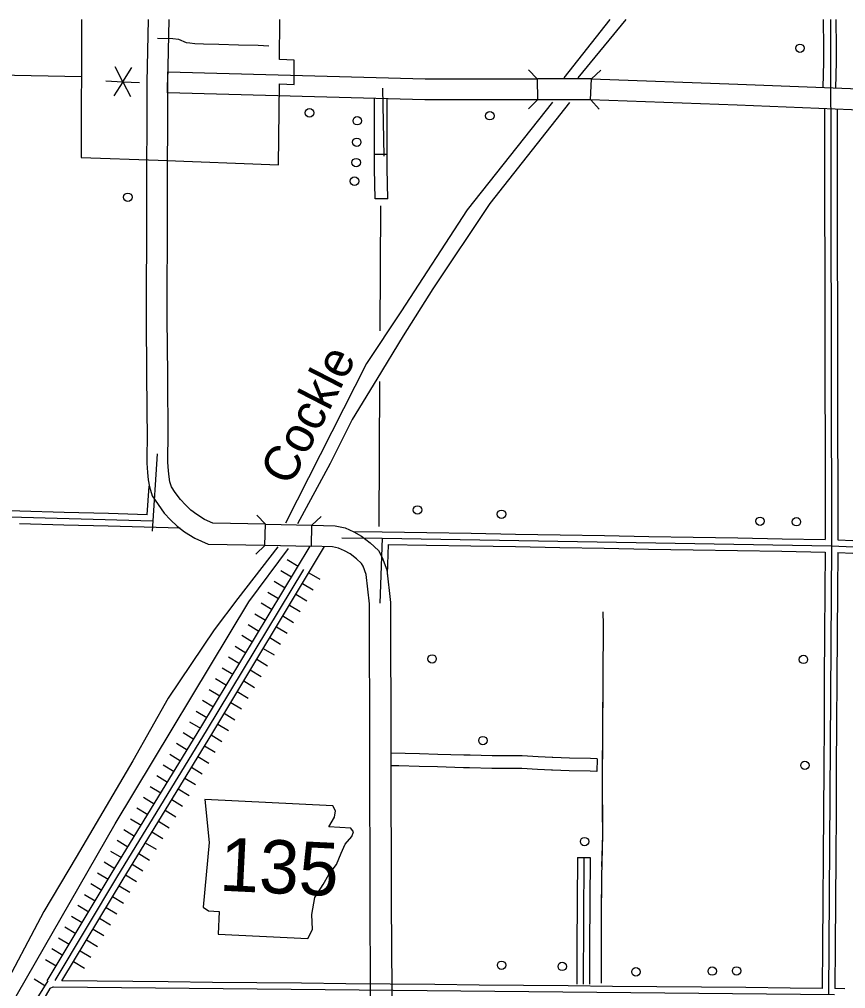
# Model space of a CAD drawing. Extents: x -4306 to 3843, y 131 to 8053.
# Drawn here: x -1822 to -251, y 6210 to 8053 of the extents above; entities that cross this region are included whole.
import ezdxf

# ---------------------------------------------------------------- set-up
doc = ezdxf.new("R2010")
doc.units = 0
for name, color, linetype in [('10', 7, 'Continuous'), ('21', 7, 'Continuous'), ('29', 7, 'Continuous'), ('32', 7, 'Continuous'), ('33', 7, 'Continuous'), ('37', 7, 'Continuous'), ('43', 7, 'Continuous'), ('46', 7, 'Continuous'), ('48', 7, 'Continuous'), ('5', 7, 'Continuous'), ('56', 7, 'Continuous'), ('6', 7, 'Continuous')]:
    doc.layers.add(name, color=color, linetype=linetype)

msp = doc.modelspace()

# ---------------------------------------------------------------- linework, layer by layer
at = {"layer": '10'}
for p, q in [((-1577, 8053), (-1579.6, 7933.8)), ((-1539.6, 7933.4), (-1537, 8053)), ((-1540, 7913.1), (-1539.4, 7953.1)), ((-1579.6, 7933.8), (-1579.9, 7691.3)), ((-1539.9, 7691.2), (-1539.6, 7933.4)), ((-837.1, 7940), (-837, 7900)), ((-746.1, 7940.2), (-836.3, 7940)), ((-734.1, 7939.8), (-746.1, 7940.2)), ((-736.1, 7899.8), (-734.1, 7939.8)), ((-734.1, 7939.8), (-455.6, 7929.7)), ((-455.6, 7929.7), (-87, 7915.2)), ((-746.8, 7900.2), (-837.2, 7900)), ((-736.1, 7899.8), (-746.8, 7900.2)), ((-457.2, 7889.8), (-736.1, 7899.8)), ((-88, 7875.2), (-457.2, 7889.8)), ((-1579.9, 7691.3), (-1580.5, 7484.2)), ((-1540.5, 7484.2), (-1539.9, 7691.2)), ((-1580.5, 7484.2), (-1579.8, 7377.2)), ((-1539.8, 7377.4), (-1540.5, 7484.2)), ((-1579.8, 7377.2), (-1579, 7253.4)), ((-1539, 7253.3), (-1539.8, 7377.4)), ((-1579, 7253.4), (-1579.2, 7227.1)), ((-1539.2, 7227), (-1539, 7253.3)), ((-1579.2, 7227.1), (-1579.2, 7209.6)), ((-1539.2, 7211.1), (-1539.2, 7227)), ((-1579.2, 7209.6), (-1577.9, 7191.8)), ((-1538, 7194.8), (-1539.2, 7211.1)), ((-1577.9, 7191.8), (-1576.8, 7177.9)), ((-1537.1, 7183), (-1538, 7194.8)), ((-1576.8, 7177.9), (-1574.4, 7164.4)), ((-1535.5, 7173.9), (-1537.1, 7183)), ((-1532.5, 7164.3), (-1535.5, 7173.9)), ((-1574.4, 7164.4), (-1569, 7146.9)), ((-1525.3, 7153.7), (-1532.5, 7164.3)), ((-1515.4, 7140), (-1525.3, 7153.7)), ((-1569, 7146.9), (-1558.1, 7130.8)), ((-1506, 7130), (-1515.4, 7140)), ((-1558.1, 7130.8), (-1546.3, 7114.5)), ((-1546.3, 7114.5), (-1534.4, 7101.7)), ((-1495.6, 7120.2), (-1506, 7130)), ((-1484.4, 7111.4), (-1495.6, 7120.2)), ((-1534.4, 7101.7), (-1521.6, 7089.8)), ((-1469.6, 7101.9), (-1484.4, 7111.4)), ((-1454.1, 7095.3), (-1469.6, 7101.9)), ((-1353.5, 7093.3), (-1454.1, 7095.3)), ((-1521.6, 7089.8), (-1507.6, 7078.8)), ((-1507.6, 7078.8), (-1488.3, 7066.4)), ((-1355, 7053.1), (-1353.5, 7093.1)), ((-1353.5, 7093.1), (-1265.3, 7091.2)), ((-1266.1, 7051.2), (-1265.5, 7091.2)), ((-1265.5, 7091.2), (-1221.5, 7090.2)), ((-1221.5, 7090.2), (-1202.6, 7086.2)), ((-1202.6, 7086.2), (-1185.9, 7078.7)), ((-1185.9, 7078.7), (-1171, 7070.8)), ((-1488.3, 7066.4), (-1462.6, 7055.5)), ((-1171, 7070.8), (-1154.7, 7058)), ((-1154.7, 7058), (-1139.3, 7043.4)), ((-1462.6, 7055.5), (-1355, 7053.3)), ((-1355, 7053.1), (-1266.1, 7051.2)), ((-1226.2, 7050.3), (-1266.1, 7051.2)), ((-1215.1, 7048), (-1226.2, 7050.3)), ((-1203.4, 7042.7), (-1215.1, 7048)), ((-1192.9, 7037.2), (-1203.4, 7042.7)), ((-1139.3, 7043.4), (-1131.8, 7029.9)), ((-1180.9, 7027.7), (-1192.9, 7037.2)), ((-1171.2, 7018.6), (-1180.9, 7027.7)), ((-1131.8, 7029.9), (-1123.4, 7006.8)), ((-1168.3, 7013.3), (-1171.2, 7018.6)), ((-1162.7, 6997.6), (-1168.3, 7013.3)), ((-1123.4, 7006.8), (-1116.2, 6944.1)), ((-1156.2, 6941.8), (-1162.7, 6997.6)), ((-1154.7, 6376.4), (-1156.2, 6941.8)), ((-1116.2, 6944.1), (-1114.6, 6374.8))]:
    msp.add_line(p, q, dxfattribs=at)
for points in [[(-1539.4, 7953.1), (-1050.4, 7939.7), (-836.3, 7940)], [(-837.2, 7900), (-1051, 7899.7), (-1540, 7913.1)], [(-1115.9, 5392.1), (-1117, 5396), (-1133.5, 5434.2), (-1148.9, 5491), (-1153.2, 5529.9), (-1154.3, 5556.1), (-1153.9, 6206.8), (-1154.7, 6376.4)], [(-1114.6, 6374.8), (-1113.9, 6206.9), (-1114.3, 5556.9), (-1113.3, 5533), (-1109.5, 5498.5), (-1095.6, 5447.4), (-1079.2, 5409.3), (-1073.9, 5390.1)]]:
    msp.add_lwpolyline(points, dxfattribs=at)
at = {"layer": '21'}
msp.add_lwpolyline([(-1469.2, 6570), (-1461, 6488.3), (-1472.4, 6365.5), (-1461.9, 6358.2), (-1441.6, 6357.2), (-1443.8, 6314), (-1273.4, 6305.6), (-1264.4, 6322.8), (-1265.8, 6351.3), (-1260.1, 6383.6), (-1244, 6408.5), (-1233.6, 6427), (-1219.1, 6446.6), (-1209.9, 6467.9), (-1202.3, 6485.1), (-1189.4, 6499.4), (-1186.2, 6508.7), (-1191.3, 6515.7), (-1233.2, 6517.8), (-1222.8, 6536.2), (-1220.9, 6548.4), (-1226, 6558)], close=True, dxfattribs=at)
at = {"layer": '29'}
for p, q in [((-1312.4, 7025.9), (-1291.9, 7013.5)), ((-1324.8, 7005.3), (-1304.3, 6993)), ((-1337.2, 6984.8), (-1316.7, 6972.4)), ((-1271.3, 7001.1), (-1250.8, 6988.8)), ((-1283.7, 6980.6), (-1263.1, 6968.2)), ((-1349.6, 6964.2), (-1329, 6951.8)), ((-1349.6, 6964.2), (-1329, 6951.8)), ((-1296.1, 6960), (-1275.5, 6947.6)), ((-1362, 6943.7), (-1341.4, 6931.3)), ((-1308.5, 6939.5), (-1287.9, 6927.1)), ((-1308.5, 6939.5), (-1287.9, 6927.1)), ((-1374.4, 6923.1), (-1353.8, 6910.7)), ((-1320.9, 6918.9), (-1300.3, 6906.5)), ((-1386.8, 6902.5), (-1366.2, 6890.2)), ((-1386.8, 6902.5), (-1366.2, 6890.2)), ((-1333.2, 6898.3), (-1312.7, 6885.9)), ((-1399.1, 6882), (-1378.6, 6869.6)), ((-1345.6, 6877.8), (-1325.1, 6865.4)), ((-1345.6, 6877.8), (-1325.1, 6865.4)), ((-1411.5, 6861.4), (-1391, 6849)), ((-1358, 6857.2), (-1337.5, 6844.8)), ((-1423.9, 6840.9), (-1403.3, 6828.5)), ((-1423.9, 6840.9), (-1403.3, 6828.5)), ((-1370.4, 6836.6), (-1349.8, 6824.3)), ((-1436.3, 6820.3), (-1415.7, 6807.9)), ((-1448.7, 6799.7), (-1428.1, 6787.3)), ((-1382.8, 6816.1), (-1362.2, 6803.7)), ((-1382.8, 6816.1), (-1362.2, 6803.7)), ((-1395.2, 6795.5), (-1374.6, 6783.1)), ((-1461.1, 6779.2), (-1440.5, 6766.8)), ((-1461.1, 6779.2), (-1440.5, 6766.8)), ((-1407.5, 6775), (-1387, 6762.6)), ((-1473.4, 6758.6), (-1452.9, 6746.2)), ((-1419.9, 6754.4), (-1399.4, 6742)), ((-1419.9, 6754.4), (-1399.4, 6742)), ((-1485.8, 6738), (-1465.3, 6725.7)), ((-1432.3, 6733.8), (-1411.8, 6721.5)), ((-1498.1, 6717.7), (-1477.6, 6705.2)), ((-1498.1, 6717.7), (-1477.6, 6705.2)), ((-1444.7, 6713.3), (-1424.1, 6700.9)), ((-1510.6, 6697.2), (-1490.1, 6684.7)), ((-1457.1, 6692.7), (-1436.7, 6680.1)), ((-1457.1, 6692.7), (-1436.7, 6680.1)), ((-1523.1, 6676.7), (-1502.6, 6664.2)), ((-1469.6, 6672.2), (-1449.2, 6659.7)), ((-1535.6, 6656.2), (-1515.2, 6643.7)), ((-1535.6, 6656.2), (-1515.2, 6643.7)), ((-1548.2, 6635.8), (-1527.7, 6623.2)), ((-1482.2, 6651.7), (-1461.7, 6639.2)), ((-1560.7, 6615.3), (-1540.2, 6602.8)), ((-1494.7, 6631.2), (-1474.2, 6618.7)), ((-1494.7, 6631.2), (-1474.2, 6618.7)), ((-1507.2, 6610.7), (-1486.7, 6598.2)), ((-1573.2, 6594.8), (-1552.7, 6582.3)), ((-1573.2, 6594.8), (-1552.7, 6582.3)), ((-1519.7, 6590.2), (-1499.2, 6577.7)), ((-1585.7, 6574.3), (-1565.2, 6561.8)), ((-1532.2, 6569.8), (-1511.7, 6557.3)), ((-1532.2, 6569.8), (-1511.7, 6557.3)), ((-1598.2, 6553.8), (-1577.7, 6541.3)), ((-1544.7, 6549.3), (-1524.2, 6536.8)), ((-1610.7, 6533.3), (-1590.2, 6520.8)), ((-1610.7, 6533.3), (-1590.2, 6520.8)), ((-1557.2, 6528.8), (-1536.8, 6516.3)), ((-1623.2, 6512.9), (-1602.8, 6500.3)), ((-1569.8, 6508.3), (-1549.3, 6495.8)), ((-1569.8, 6508.3), (-1549.3, 6495.8)), ((-1635.8, 6492.4), (-1615.3, 6479.9)), ((-1582.3, 6487.8), (-1561.8, 6475.3)), ((-1648.3, 6471.9), (-1627.8, 6459.4)), ((-1648.3, 6471.9), (-1627.8, 6459.4)), ((-1660.8, 6451.4), (-1640.3, 6438.9)), ((-1594.8, 6467.4), (-1574.3, 6454.8)), ((-1673.3, 6430.6), (-1652.8, 6418.3)), ((-1607.3, 6446.9), (-1586.8, 6434.4)), ((-1607.3, 6446.9), (-1586.8, 6434.4)), ((-1619.8, 6426.4), (-1599.3, 6413.9)), ((-1685.7, 6410.1), (-1665.1, 6397.7)), ((-1685.7, 6410.1), (-1665.1, 6397.7)), ((-1632.2, 6405.9), (-1611.6, 6393.6)), ((-1698.1, 6389.5), (-1677.5, 6377.1)), ((-1644.5, 6385.3), (-1624, 6373)), ((-1644.5, 6385.3), (-1624, 6373)), ((-1710.4, 6368.9), (-1689.8, 6356.5)), ((-1656.9, 6364.8), (-1636.3, 6352.4)), ((-1722.8, 6348.3), (-1702.2, 6336)), ((-1722.8, 6348.3), (-1702.2, 6336)), ((-1669.3, 6344.2), (-1648.7, 6331.8)), ((-1735.1, 6327.8), (-1714.5, 6315.4)), ((-1681.6, 6323.6), (-1661, 6311.3)), ((-1681.6, 6323.6), (-1661, 6311.3)), ((-1747.5, 6307.2), (-1726.9, 6294.8)), ((-1694, 6303), (-1673.4, 6290.7)), ((-1759.8, 6286.6), (-1739.3, 6274.2)), ((-1759.8, 6286.6), (-1739.3, 6274.2)), ((-1772.2, 6266), (-1751.6, 6253.7)), ((-1706.3, 6282.5), (-1685.7, 6270.1)), ((-1718.7, 6261.9), (-1698.1, 6249.5)), ((-1718.7, 6261.9), (-1698.1, 6249.5)), ((-1793.8, 6229.1), (-1773.3, 6216.5))]:
    msp.add_line(p, q, dxfattribs=at)
at = {"layer": '32'}
for p, q in [((-293.7, 8053), (-293.1, 7999.3)), ((-279.5, 8053), (-277.8, 7052)), ((-269.7, 8053), (-269.1, 7999.5)), ((-293.1, 7999.3), (-292.8, 7972.3)), ((-269.1, 7999.5), (-268.8, 7972.1)), ((-292.8, 7972.3), (-294.2, 7923.4)), ((-268.8, 7972.1), (-270.2, 7922.4)), ((-1128.2, 7793.2), (-1130.9, 7921.9)), ((-1146.4, 7880.6), (-1146.5, 7902.3)), ((-1122.4, 7880.7), (-1122.5, 7901.6)), ((-1146.6, 7852.2), (-1146.4, 7879.7)), ((-1146.4, 7879.7), (-1146.4, 7880.6)), ((-1122.6, 7852.1), (-1122.4, 7879.6)), ((-1122.4, 7879.6), (-1122.4, 7880.7)), ((-291.2, 7883.2), (-291.1, 7851.3)), ((-267.2, 7882.2), (-267.1, 7851.4)), ((-1146.6, 7807.4), (-1146.6, 7852.2)), ((-1122.6, 7807.5), (-1122.6, 7852.1)), ((-291.1, 7851.3), (-291, 7766.8)), ((-267.1, 7851.4), (-267, 7766.9)), ((-1146.5, 7796.1), (-1146.6, 7807.4)), ((-1122.5, 7796.3), (-1146.5, 7796.1)), ((-1146.3, 7768.9), (-1146.5, 7796.1)), ((-1122.5, 7796.3), (-1122.6, 7807.5)), ((-1122.3, 7769.2), (-1122.5, 7796.3)), ((-1145.2, 7711.5), (-1146.3, 7768.9)), ((-1121.2, 7711.9), (-1122.3, 7769.2)), ((-291, 7766.8), (-290.9, 7682.3)), ((-267, 7766.9), (-266.9, 7682.4)), ((-1121.2, 7711.9), (-1145.2, 7711.5)), ((-290.9, 7682.3), (-290.7, 7597.8)), ((-266.9, 7682.4), (-266.7, 7597.9)), ((-290.7, 7597.8), (-290.6, 7513.4)), ((-266.7, 7597.9), (-266.6, 7513.4)), ((-290.6, 7513.4), (-290.4, 7428.9)), ((-266.6, 7513.4), (-266.4, 7428.9)), ((-290.4, 7428.9), (-290.3, 7344.4)), ((-266.4, 7428.9), (-266.3, 7344.4)), ((-290.3, 7344.4), (-290.1, 7259.9)), ((-266.3, 7344.4), (-266.1, 7259.9)), ((-290.1, 7259.9), (-290, 7175.4)), ((-266.1, 7259.9), (-266, 7175.4)), ((-1568.5, 7080.3), (-1559.2, 7227)), ((-290, 7175.4), (-289.9, 7090.9)), ((-266, 7175.4), (-265.9, 7091)), ((-1578.6, 7111.3), (-1575.2, 7165.3)), ((-1821, 7118), (-1899.3, 7120.2)), ((-1736.6, 7115.6), (-1821, 7118)), ((-1652.1, 7113.3), (-1736.6, 7115.6)), ((-1578.6, 7111.3), (-1652.1, 7113.3)), ((-1568, 7099), (-1892.8, 7108)), ((-1737.2, 7091.6), (-1821.7, 7094)), ((-1652.8, 7089.3), (-1737.2, 7091.6)), ((-1516.2, 7085.5), (-1652.8, 7089.3)), ((-1186.6, 7079.1), (-1132, 7079)), ((-1131.8, 7079), (-1047.3, 7077.5)), ((-1047.3, 7077.5), (-962.9, 7076)), ((-962.9, 7076), (-878.4, 7074.6)), ((-289.9, 7090.9), (-289.8, 7064.2)), ((-265.9, 7091), (-265.8, 7063.5)), ((-1208.9, 7067.1), (-1132, 7067)), ((-1132, 7067), (-1136.2, 6943)), ((-1132, 7067), (-277.8, 7052)), ((-878.4, 7074.6), (-793.9, 7073.1)), ((-793.9, 7073.1), (-709.4, 7071.6)), ((-709.4, 7071.6), (-625, 7070.1)), ((-625, 7070.1), (-540.5, 7068.6)), ((-540.5, 7068.6), (-456, 7067.1)), ((-456, 7067.1), (-371.5, 7065.7)), ((-371.5, 7065.7), (-289.8, 7064.2)), ((-265.8, 7063.5), (-202.3, 7060.6)), ((-1120.4, 7054.8), (-1122.4, 6997.5)), ((-1120.4, 7054.8), (-1047.8, 7053.5)), ((-1047.8, 7053.5), (-963.3, 7052)), ((-963.3, 7052), (-878.8, 7050.6)), ((-878.8, 7050.6), (-794.3, 7049.1)), ((-794.3, 7049.1), (-709.9, 7047.6)), ((-709.9, 7047.6), (-625.4, 7046.1)), ((-625.4, 7046.1), (-540.9, 7044.6)), ((-540.9, 7044.6), (-456.4, 7043.1)), ((-456.4, 7043.1), (-372, 7041.7)), ((-372, 7041.7), (-289.9, 7040.2)), ((-289.9, 7040.2), (-290.4, 6967.6)), ((-277.8, 7052), (-283.5, 6198.8)), ((-277.8, 7052), (484, 7017.2)), ((-265.9, 7039.5), (-266.4, 6967.4)), ((-265.9, 7039.5), (-203.4, 7036.6)), ((-1281.6, 7007.3), (-1466.4, 6700.5)), ((-290.4, 6967.6), (-290.9, 6883.1)), ((-266.4, 6967.4), (-266.9, 6883)), ((-290.9, 6883.1), (-291.5, 6798.6)), ((-266.9, 6883), (-267.5, 6798.5)), ((-291.5, 6798.6), (-292, 6714.1)), ((-267.5, 6798.5), (-268, 6714)), ((-292, 6714.1), (-292.6, 6629.7)), ((-268, 6714), (-268.6, 6629.5)), ((-1466.4, 6700.5), (-1634.9, 6424.7)), ((-1061.1, 6656.6), (-1115.4, 6657.9)), ((-1026, 6655.7), (-1061.1, 6656.6)), ((-976.6, 6654.2), (-1026, 6655.7)), ((-965, 6653.9), (-976.6, 6654.2)), ((-922.9, 6652.7), (-965, 6653.9)), ((-892.5, 6652.7), (-922.9, 6652.7)), ((-865.8, 6652.7), (-892.5, 6652.7)), ((-835.2, 6650.9), (-865.8, 6652.7)), ((-1100.4, 6633.6), (-1115.4, 6633.8)), ((-1061.7, 6632.6), (-1100.4, 6633.6)), ((-809.1, 6649.6), (-835.2, 6650.9)), ((-807.6, 6649.5), (-809.1, 6649.6)), ((-775.6, 6648.3), (-807.6, 6649.5)), ((-736, 6647.9), (-775.6, 6648.3)), ((-723, 6647.2), (-736, 6647.9)), ((-723, 6647.2), (-724.2, 6623.3)), ((-1026.7, 6631.7), (-1061.7, 6632.6)), ((-977.3, 6630.2), (-1026.7, 6631.7)), ((-965.7, 6629.9), (-977.3, 6630.2)), ((-923.3, 6628.7), (-965.7, 6629.9)), ((-892.5, 6628.7), (-923.3, 6628.7)), ((-866.5, 6628.7), (-892.5, 6628.7)), ((-836.4, 6626.9), (-866.5, 6628.7)), ((-810.2, 6625.6), (-836.4, 6626.9)), ((-808.5, 6625.6), (-810.2, 6625.6)), ((-776.2, 6624.3), (-808.5, 6625.6)), ((-736.7, 6623.9), (-776.2, 6624.3)), ((-724.2, 6623.3), (-736.7, 6623.9)), ((-292.6, 6629.7), (-293.2, 6545.2)), ((-268.6, 6629.5), (-269.2, 6545)), ((-293.2, 6545.2), (-293.7, 6460.7)), ((-269.2, 6545), (-269.7, 6460.5)), ((-760.9, 6459.9), (-761.3, 6375.4)), ((-760.9, 6459.9), (-736.9, 6459.8)), ((-748.9, 6459.9), (-750.1, 6218.7)), ((-736.9, 6459.8), (-737.3, 6375.3)), ((-293.7, 6460.7), (-294.3, 6376.2)), ((-269.7, 6460.5), (-270.3, 6376)), ((-1634.9, 6424.7), (-1754.5, 6225.6)), ((-761.3, 6375.4), (-761.7, 6290.9)), ((-294.3, 6376.2), (-294.9, 6291.7)), ((-270.3, 6376), (-270.9, 6291.6)), ((-737.3, 6375.3), (-737.7, 6290.8)), ((-761.7, 6290.9), (-762.1, 6218.8)), ((-737.7, 6290.8), (-738.1, 6218.7)), ((-294.9, 6291.7), (-295.4, 6210.8)), ((-270.9, 6291.6), (-271.4, 6210.6)), ((-1763.8, 6210.7), (-1874.4, 6022.8)), ((-1767.9, 6225.3), (-1817.7, 6144.6)), ((-1758.3, 6213), (-1763.8, 6210.7)), ((-1756.9, 6213.2), (-1758.3, 6213)), ((-271.9, 6198.6), (-1756.9, 6213.2)), ((-1539, 6223), (-1740.8, 6225)), ((-1454.5, 6222.2), (-1539, 6223)), ((-1370.1, 6221.4), (-1454.5, 6222.2)), ((-1285.6, 6220.5), (-1370.1, 6221.4)), ((-1201.1, 6219.7), (-1285.6, 6220.5)), ((-1116.6, 6218.9), (-1201.1, 6219.7)), ((-1032.1, 6218), (-1116.6, 6218.9)), ((-947.6, 6217.2), (-1032.1, 6218)), ((-863.2, 6216.4), (-947.6, 6217.2)), ((-778.7, 6215.5), (-863.2, 6216.4)), ((-694.2, 6214.7), (-778.7, 6215.5)), ((-609.7, 6213.9), (-694.2, 6214.7)), ((-525.2, 6213.1), (-609.7, 6213.9)), ((-440.7, 6212.2), (-525.2, 6213.1)), ((-356.2, 6211.4), (-440.7, 6212.2)), ((-295.4, 6210.8), (-356.2, 6211.4)), ((-252.7, 6210.1), (-271.6, 6210.6))]:
    msp.add_line(p, q, dxfattribs=at)
at = {"layer": '33'}
for p, q in [((-1559, 8017.2), (-1530.1, 8016.9)), ((-1530.1, 8016.9), (-1519.2, 8015.3)), ((-1519.2, 8015.3), (-1504.8, 8009.2)), ((-1504.8, 8009.2), (-1497.4, 8008.1)), ((-1497.4, 8008.1), (-1488.1, 8006.8)), ((-1488.1, 8006.8), (-1471.8, 8006.6)), ((-1471.8, 8006.6), (-1442.3, 8005.9)), ((-1442.3, 8005.9), (-1405.2, 8004.4)), ((-1405.2, 8004.4), (-1367.5, 8003.9)), ((-1367.5, 8003.9), (-1347.2, 8002.6))]:
    msp.add_line(p, q, dxfattribs=at)
at = {"layer": '37'}
for p, q in [((-837, 7920), (-837, 7920)), ((-734.8, 7919.8), (-734.8, 7919.8)), ((-1248.1, 7107.8), (-1265.5, 7091.2)), ((-1354.3, 7073.1), (-1354.3, 7073.1)), ((-1265.9, 7071.2), (-1265.9, 7071.2))]:
    msp.add_line(p, q, dxfattribs=at)
for points in [[(-837.1, 7940), (-854.1, 7957)], [(-716.6, 7956.1), (-734.1, 7939.8)], [(-853.9, 7883), (-837, 7900)], [(-735.6, 7899.8), (-719.2, 7882.2)], [(-1353.9, 7093.1), (-1370.5, 7110.5)], [(-1372.1, 7036.5), (-1354.7, 7053.1)]]:
    msp.add_lwpolyline(points, dxfattribs=at)
at = {"layer": '43'}
for points in [[(-699.5, 8053), (-786.9, 7941.6)], [(-668.7, 8053), (-759.9, 7941.6)], [(-808, 7895.4), (-970.4, 7691.1), (-1096.7, 7496.9), (-1162, 7398.5), (-1315.8, 7095)], [(-775.7, 7895.2), (-927.1, 7702.9), (-1035.6, 7540.7), (-1091.8, 7451.6), (-1142.1, 7369), (-1189, 7292), (-1231, 7208.6), (-1293.2, 7093.9)], [(-1330.4, 7050.5), (-1406.5, 6952.3), (-1451.4, 6892.2), (-1538.8, 6762.8), (-1606.3, 6643.7), (-1713.9, 6460.4), (-1775.4, 6357), (-1861.2, 6194.6), (-1921.7, 6085.7), (-1963.4, 6016.6), (-2014.8, 5943)], [(-1877.3, 6111.1), (-1639.5, 6523.5), (-1385.4, 6945.6), (-1310.2, 7047.2)], [(-715.1, 6220.7), (-715.1, 6343.3), (-714.7, 6422.2), (-712.8, 6503.4), (-713.1, 6617.6), (-711.6, 6801), (-711.5, 6901.8), (-712, 6926.9)], [(-711.5, 6864.9), (-711.5, 6901.8), (-712, 6926.9)], [(-711.8, 6780.4), (-711.6, 6801), (-711.6, 6843.8)], [(-712.2, 6727.6), (-712, 6759.3)], [(-712.4, 6695.9), (-712.2, 6727.6)], [(-713, 6611.4), (-713.1, 6617.6), (-712.6, 6674.8)], [(-712.9, 6526.9), (-713, 6590.3)], [(-714.2, 6442.5), (-712.8, 6503.4), (-712.8, 6505.8)], [(-715.1, 6358), (-714.7, 6421.4)], [(-715.1, 6273.5), (-715.1, 6336.9)], [(-715.1, 6220.7), (-715.1, 6252.4)]]:
    msp.add_lwpolyline(points, dxfattribs=at)
at = {"layer": '46'}
for p, q in [((-1476.6, 6706.8), (-1269.2, 7051.3)), ((-1456.1, 6694.3), (-1241.5, 7050.7)), ((-1645.2, 6430.9), (-1476.6, 6706.8)), ((-1624.7, 6418.4), (-1456.1, 6694.3)), ((-1768.7, 6225.3), (-1645.2, 6430.9)), ((-1740.8, 6225), (-1624.7, 6418.4))]:
    msp.add_line(p, q, dxfattribs=at)
at = {"layer": '48'}
for p, q in [((-1625.1, 7934.5), (-1639.7, 7963)), ((-1625.1, 7934.5), (-1607.8, 7961.4)), ((-1657.1, 7936.1), (-1625.1, 7934.5)), ((-1625.1, 7934.5), (-1642.4, 7907.6)), ((-1625.1, 7934.5), (-1593.1, 7933)), ((-1625.1, 7934.5), (-1610.5, 7906.1))]:
    msp.add_line(p, q, dxfattribs=at)
at = {"layer": '5'}
for p, q in [((-1703.8, 7943.7), (-1968.1, 7948.7)), ((-1135.9, 7460.7), (-1134.7, 7698.7)), ((-1137.9, 7089.2), (-1136.4, 7364.7))]:
    msp.add_line(p, q, dxfattribs=at)
at = {"layer": '56'}
for centre in [(-337.7, 7998), (-1270.1, 7875.3), (-1179.3, 7860.2), (-927.4, 7869.7), (-1180.4, 7819.4), (-1181.4, 7780.7), (-1184.6, 7745.4), (-1615.5, 7714.8), (-1064.8, 7120.3), (-905.2, 7112.2), (-413.7, 7098.9), (-344.5, 7097.9), (-1037.1, 6837.1), (-331.2, 6836.2), (-940.4, 6681.8), (-328.3, 6634.8), (-747.2, 6489.9), (-905, 6254.8), (-789.7, 6252.5), (-649.5, 6242.3), (-504.4, 6243.7), (-458.3, 6244)]:
    msp.add_circle(centre, 8, dxfattribs=at)
at = {"layer": '6'}
msp.add_lwpolyline([(-1703.4, 8053), (-1704.3, 7790.4), (-1557.7, 7785.5), (-1329.1, 7776.6), (-1327.4, 7930.3), (-1299.6, 7929.2), (-1299.1, 7975.6), (-1327, 7976.7), (-1326.3, 8053)], dxfattribs=at)

# ---------------------------------------------------------------- texts
at = {"layer": '21'}
msp.add_text('135', height=101.29, rotation=357.2006, dxfattribs=at).set_placement((-1442.8, 6396.8))
at = {"layer": '43'}
msp.add_text('Cockle', height=67.59, rotation=62.8132, dxfattribs=at).set_placement((-1306.6, 7163.6))

doc.saveas('drawing.dxf')
